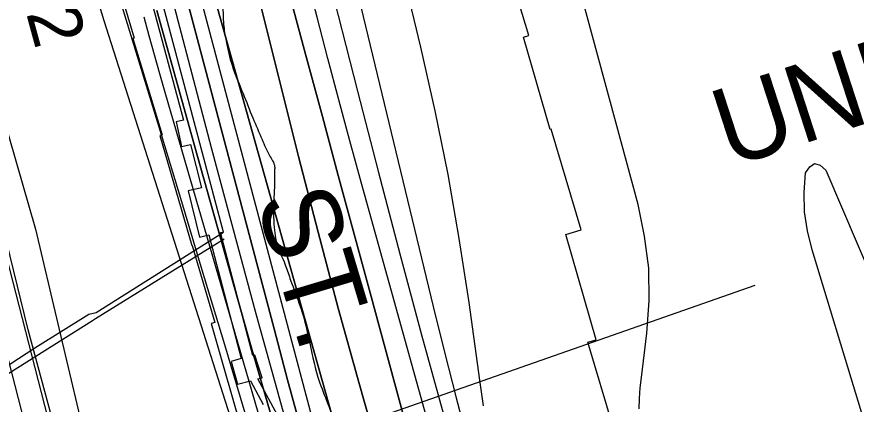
# Model space of a CAD drawing. Extents: x 3405885 to 3443815, y 558517 to 583997.
# Drawn here: x 3413539 to 3414615, y 577127 to 577623 of the extents above; entities that cross this region are included whole.
import ezdxf

# ---------------------------------------------------------------- set-up
doc = ezdxf.new("R2010")
doc.units = 0
for name, color, linetype in [('V-CHAN-DOCK', 7, 'Continuous'), ('V-FLOD-BASE', 7, 'Continuous'), ('V-LEVE-TOET', 7, 'Continuous'), ('V-RIVR-EDGE', 7, 'Continuous'), ('V-RIVR-RANG', 7, 'Continuous'), ('V-RRAP-RVMT', 7, 'Continuous'), ('V-RRAP-RVMT-IDEN', 7, 'Continuous'), ('V-SURV-LINE', 7, 'Continuous'), ('V-TOPO-DPTH', 7, 'Continuous'), ('V-TOPO-GNAM-IDEN', 7, 'Continuous'), ('V-TOPO-MAJR', 7, 'Continuous'), ('V-TOPO-MINR', 7, 'Continuous'), ('V-TOPO-WATR', 7, 'Continuous'), ('V-UTIL-LINE', 7, 'Continuous')]:
    doc.layers.add(name, color=color, linetype=linetype)

msp = doc.modelspace()

# ---------------------------------------------------------------- linework, layer by layer
at = {"layer": 'V-CHAN-DOCK'}
for points in [[(3414098.9, 576327.5), (3413981.9, 576772.3), (3413984.8, 576773), (3413976.8, 576806), (3413974, 576805.3), (3413906.9, 577051.1), (3413848.5, 577159.2), (3413854, 577160.6), (3413844.4, 577189.7), (3413841.9, 577189), (3413800.6, 577346.9), (3413804.2, 577347.4), (3413685.9, 577792.6)], [(3413710.8, 577648.5), (3413752.9, 577490.9), (3413743.5, 577488.6), (3413750.4, 577457.2), (3413762.1, 577459.5), (3413775.9, 577404.1), (3413759, 577400.3), (3413773.5, 577340.9), (3413785.5, 577343.7), (3413827.1, 577185.1), (3413814.2, 577181.6), (3413822.2, 577152.6), (3413838.8, 577156.7), (3413855.3, 577126.4)]]:
    msp.add_lwpolyline(points, dxfattribs=at)
at = {"layer": 'V-FLOD-BASE'}
msp.add_lwpolyline([(3413966.8, 575593.2), (3413930, 575533.2), (3413867.4, 575424.5), (3413866.3, 575435.7), (3413891.6, 575528.1), (3413926.7, 575661.7), (3413958.1, 575773.5), (3413962.9, 575792.9), (3413964.2, 575799.4), (3413964.2, 575804.7), (3413956.2, 575840.2), (3413920.9, 575949.5), (3413875.3, 576086.5), (3413833.1, 576215.9), (3413788.5, 576347.1), (3413730.7, 576515.5), (3413715.1, 576565.7), (3413696.7, 576641.3), (3413660.7, 576803.1), (3413634.6, 576914.3), (3413596.7, 577063.8), (3413554.1, 577222), (3413512.2, 577391.5)], dxfattribs=at)
at = {"layer": 'V-LEVE-TOET'}
msp.add_lwpolyline([(3413499, 577627.3), (3413496.6, 577619.1), (3413497.1, 577610.8), (3413502.2, 577577.8), (3413521.1, 577498.1), (3413563.2, 577351), (3413591.9, 577229.9), (3413633.2, 577054.6), (3413679.1, 576870.9), (3413715.7, 576698.5), (3413753.1, 576555.6), (3413784.9, 576453.4), (3413834.6, 576306.2), (3413880.9, 576173.3), (3413933, 576029.7), (3413974, 575893.8), (3413991.8, 575823.5), (3413994.1, 575811.1), (3413994, 575804.1), (3413975.8, 575718.7), (3413949.8, 575619.2)], dxfattribs=at)
at = {"layer": 'V-RIVR-EDGE'}
msp.add_spline([(3412820.9, 582098.3), (3412817.8, 582058), (3412815.6, 582029.5), (3412817.7, 582007.9), (3412825.7, 581980.1), (3412850.3, 581879.9), (3412863.7, 581832.7), (3412872, 581799.1), (3412892.3, 581722.3), (3412903.2, 581678.4), (3412909.6, 581634.8), (3412920.5, 581599), (3412934, 581569.3), (3412943.4, 581548.5), (3412954.7, 581511.2), (3412955.3, 581484.9), (3412959.7, 581464), (3412965.1, 581459.6), (3412977.9, 581445), (3412992.4, 581409.1), (3413006.5, 581353.1), (3413015.2, 581302.3), (3413018.7, 581260.3), (3413013.9, 581236.1), (3413008.8, 581220.1), (3413005.1, 581206.5), (3413003.6, 581194.5), (3413004.7, 581180.2), (3413009.3, 581149.1), (3413020.6, 581117.3), (3413042, 581073), (3413073, 581031.3), (3413081, 581018.1), (3413088.7, 580999.8), (3413094.4, 580977.9), (3413100.2, 580939.1), (3413102.7, 580912), (3413106.3, 580894.1), (3413113.5, 580861.9), (3413124.8, 580824.3), (3413140, 580781.4), (3413146.5, 580756.9), (3413148.7, 580740.1), (3413153.8, 580721.8), (3413161, 580692.6), (3413184.2, 580615.7), (3413194, 580582.5), (3413204.2, 580568.2), (3413207.8, 580561.6), (3413214, 580535.3), (3413232.1, 580461.7), (3413244, 580397.7), (3413253, 580345.1), (3413251.9, 580330.8), (3413256.4, 580258.4), (3413262.5, 580217.5), (3413264.6, 580175.4), (3413271.5, 580146.5), (3413278.7, 580117.3), (3413280.2, 580104.8), (3413276.4, 580060.6), (3413276.3, 580025.9), (3413275.6, 580012.4), (3413275.5, 580006.1), (3413277.7, 580003.2), (3413288, 580000.6), (3413298.6, 579998.4), (3413303.7, 579992.2), (3413305.5, 579985.2), (3413310.1, 579953.8), (3413314.5, 579931.1), (3413321, 579914.6), (3413327.2, 579894.5), (3413327.1, 579868.9), (3413323.4, 579842.6), (3413317.9, 579835.3), (3413316, 579824.7), (3413315.6, 579806.5), (3413320, 579780.1), (3413328, 579765.1), (3413335.6, 579758.2), (3413338.2, 579753.4), (3413338.9, 579747.5), (3413338.9, 579742.8), (3413335.5, 579730.7), (3413330.8, 579723.1), (3413327.8, 579714.3), (3413325.2, 579701.2), (3413326.7, 579689.5), (3413332.1, 579675.9), (3413338.3, 579668.2), (3413342.7, 579666.4), (3413352.6, 579666.7), (3413357.3, 579663.4), (3413365.3, 579652.4), (3413371.9, 579635.2), (3413374.8, 579618.4), (3413377.6, 579592.5), (3413379.4, 579557.4), (3413373.8, 579521.6), (3413375.2, 579501.1), (3413382.1, 579476.9), (3413395.1, 579440), (3413408.6, 579400.8), (3413417.6, 579358.8), (3413445.2, 579297.7), (3413449.9, 579271.7), (3413449.8, 579233.3), (3413439.5, 579191.3), (3413438.7, 579182.2), (3413439.8, 579172.7), (3413446, 579161.7), (3413464.9, 579134.6), (3413487.5, 579101.6), (3413497, 579074.9), (3413502.7, 579046.4), (3413506.7, 579018.2), (3413510.6, 578990.8), (3413518.6, 578952.4), (3413529.8, 578903.8), (3413538.1, 578871.6), (3413547.9, 578834.6), (3413558.4, 578787.4), (3413566.7, 578743.2), (3413574.6, 578699.3), (3413585.1, 578637.1), (3413595.2, 578577.2), (3413599.5, 578547.5), (3413610.7, 578516.1), (3413620.2, 578504), (3413626, 578499.2), (3413635.5, 578497), (3413635.9, 578494.4), (3413634.1, 578490.1), (3413632.2, 578487.1), (3413632.2, 578479.5), (3413633.2, 578455), (3413642.2, 578391), (3413644.3, 578359.2), (3413649, 578338.7), (3413656.3, 578322.2), (3413667.6, 578313.8), (3413676, 578309), (3413684.4, 578305.3), (3413688.8, 578300.2), (3413697.9, 578288.5), (3413702.2, 578272.4), (3413709.1, 578250.8), (3413714.9, 578233.2), (3413728.7, 578187.2), (3413734.8, 578151.3), (3413738.8, 578114.4), (3413740.5, 578084), (3413746.7, 578059.2), (3413750.7, 578043.4), (3413751.3, 578020), (3413747.6, 577990.8), (3413742, 577955), (3413736.9, 577934.5), (3413735.4, 577919.6), (3413733.5, 577904.2), (3413737.1, 577880.1), (3413741.4, 577864.7), (3413741.4, 577863.2), (3413750.2, 577865.8), (3413755, 577862.8), (3413760, 577845.7), (3413773.8, 577798.1), (3413781.8, 577765.2), (3413793, 577724.9), (3413797, 577700.4), (3413803.4, 577637.2), (3413804.4, 577613.8), (3413807.7, 577591.8), (3413815.3, 577561.1), (3413829.4, 577524.9), (3413841.8, 577493.8), (3413853.8, 577466), (3413863.2, 577445.5), (3413869.8, 577431.2), (3413869.8, 577426.1), (3413869.7, 577412.9), (3413868.9, 577389.5), (3413869.2, 577353), (3413871, 577339.8), (3413873.9, 577328.5), (3413883, 577306.5), (3413889.5, 577287.9), (3413905.1, 577244.3), (3413913.5, 577211), (3413925.4, 577161.3), (3413947.6, 577101.7), (3413958.8, 577073.5), (3413969, 577057.4), (3413973, 577043.8), (3413979.9, 577014.6), (3414002, 576930.8), (3414004.5, 576907.4), (3414006.3, 576897.2), (3414015, 576880.3), (3414024.5, 576858.8), (3414031.3, 576835.7), (3414040.8, 576799.5), (3414054.2, 576750.1), (3414062.5, 576713.9), (3414069.3, 576679.9), (3414074.4, 576668.5), (3414075.1, 576663.4), (3414103.1, 576586.2), (3414107.4, 576564.6), (3414115.4, 576529.2), (3414119, 576508), (3414142.2, 576433.7), (3414153.5, 576399.3), (3414159.6, 576378.5), (3414164.7, 576348.8), (3414174.1, 576303.8), (3414178, 576275), (3414184.1, 576248.3), (3414191.1, 576234), (3414204.1, 576202.1), (3414212.1, 576179.5), (3414243, 576089.5), (3414264.8, 576025.4), (3414269.5, 576005.7), (3414269.4, 575994.4), (3414267.6, 575989.1)], degree=3, dxfattribs=at)
at = {"layer": 'V-RIVR-RANG'}
msp.add_line((3413598.5, 576968.9), (3414485.8, 577279.2), dxfattribs=at)
at = {"layer": 'V-RRAP-RVMT'}
for points in [[(3414453.7, 576492.6), (3414409.1, 576621.8), (3414406.4, 576620.8), (3414365.7, 576741.2), (3414359.7, 576739.2), (3414321.2, 576853), (3414317.2, 576851.7), (3414285.6, 576951.7), (3414313.7, 576960.2), (3414275.4, 577087.5), (3414304, 577096), (3414271.4, 577206.1), (3414281.9, 577209.2), (3414243, 577344.3), (3414262.9, 577350.2), (3414224.5, 577479.4), (3414222.9, 577478.9), (3414188.7, 577597.3), (3414195.6, 577599.4), (3414154.2, 577736.4)], [(3413652.8, 577721.4), (3413690, 577595.9), (3413688.2, 577595.4), (3413725.6, 577471.8), (3413722.8, 577471), (3413763.6, 577330.1), (3413764, 577330.2), (3413793.3, 577231.6), (3413788.3, 577230.2), (3413831.8, 577079.3), (3413835.3, 577080.3), (3413865.5, 576978.7), (3413855.2, 576975.6), (3413892.6, 576851.5), (3413887.4, 576849.9), (3413928.5, 576720.2), (3413923, 576718.4), (3413961.4, 576604.5), (3413956, 576602.7), (3413997.6, 576479.5)]]:
    msp.add_lwpolyline(points, dxfattribs=at)
at = {"layer": 'V-SURV-LINE'}
for points in [[(3413574.1, 577007.7), (3412835.6, 579881.8)], [(3412864.6, 579889.2), (3413603.1, 577015.1)]]:
    msp.add_lwpolyline(points, dxfattribs=at)
at = {"layer": 'V-TOPO-DPTH'}
for points in [[(3413870.4, 577720.3), (3413910.7, 577570.7), (3413931, 577495.3), (3413951.4, 577420), (3413971.8, 577344.6), (3413992.3, 577269.3), (3414092.8, 576899.2), (3414095.8, 576888.3), (3414098.8, 576877.5), (3414101.9, 576866.6), (3414105, 576855.8), (3414108.2, 576844.9), (3414111.5, 576834.2), (3414114.9, 576823.4), (3414118.4, 576812.7), (3414340.3, 576140.2), (3414345.1, 576125.9), (3414350, 576111.6), (3414355.1, 576097.4), (3414360.2, 576083.2), (3414623.5, 575371.4)], [(3413870.4, 577720.3), (3413910.7, 577570.7), (3413931, 577495.3), (3413951.4, 577420), (3413971.8, 577344.6), (3413992.3, 577269.3), (3414092.8, 576899.2), (3414095.8, 576888.3), (3414098.8, 576877.5), (3414101.9, 576866.6), (3414105, 576855.8), (3414108.2, 576844.9), (3414111.5, 576834.2), (3414114.9, 576823.4), (3414118.4, 576812.7), (3414340.3, 576140.2), (3414345.1, 576125.9), (3414350, 576111.6), (3414355.1, 576097.4), (3414360.2, 576083.2), (3414623.5, 575371.4)], [(3414176.3, 576509.8), (3414149.5, 576591.8), (3414072.6, 576829.5), (3414067.2, 576846.7), (3414061.8, 576864), (3414056.5, 576881.3), (3414051.4, 576898.6), (3414005.4, 577056.7), (3413978, 577153.3), (3413951.2, 577250), (3413925.5, 577347), (3413900.6, 577444.3), (3413843.2, 577673.7)], [(3414176.3, 576509.8), (3414149.5, 576591.8), (3414072.6, 576829.5), (3414067.2, 576846.7), (3414061.8, 576864), (3414056.5, 576881.3), (3414051.4, 576898.6), (3414005.4, 577056.7), (3413978, 577153.3), (3413951.2, 577250), (3413925.5, 577347), (3413900.6, 577444.3), (3413843.2, 577673.7)], [(3413754, 577659.2), (3413869.2, 577223.1), (3413886.5, 577157.9), (3413904.1, 577092.8), (3413922, 577027.8), (3413940.2, 576962.9), (3413969.6, 576858.5), (3413973.2, 576845.8), (3413976.8, 576833.1), (3413980.4, 576820.4), (3413984.1, 576807.7), (3414083.7, 576466.7)], [(3414083.7, 576466.7), (3413984.1, 576807.7), (3413980.4, 576820.4), (3413976.8, 576833.1), (3413973.2, 576845.8), (3413969.6, 576858.5), (3413940.2, 576962.9), (3413922, 577027.8), (3413904.1, 577092.8), (3413886.5, 577157.9), (3413869.2, 577223.1), (3413754, 577659.2)], [(3413669.5, 577652.8), (3413721.3, 577482.2), (3413749, 577390.6), (3413776.6, 577299), (3413804.2, 577207.3), (3413831.6, 577115.6), (3413917.5, 576827.7), (3413919.7, 576820.4), (3413921.8, 576813.1), (3413923.9, 576805.8), (3413925.9, 576798.4), (3413944.3, 576731.5), (3413955.5, 576690.7), (3413966.4, 576649.8), (3413977.1, 576608.8), (3413987.7, 576567.8), (3414103.6, 576111.6)], [(3413718.9, 577631.5), (3413770.4, 577445.8), (3413839.6, 577200.4), (3413913, 576949), (3413952.7, 576812.7), (3414019.4, 576571.6), (3414062.4, 576415.7), (3414113.9, 576220.6), (3414156.9, 576063), (3414193.2, 575932.6), (3414227.8, 575803.1), (3414306.3, 575543.2), (3414400.9, 575243.3), (3414476.2, 575016.6), (3414482.1, 574999.6), (3414486.3, 574987.7), (3414536.2, 574860.7), (3414616.6, 574655.3)], [(3414616.6, 574655.3), (3414536.2, 574860.7), (3414486.3, 574987.7), (3414482.1, 574999.6), (3414476.2, 575016.6), (3414400.9, 575243.3), (3414306.3, 575543.2), (3414227.8, 575803.1), (3414193.2, 575932.6), (3414156.9, 576063), (3414113.9, 576220.6), (3414062.4, 576415.7), (3414019.4, 576571.6), (3413952.7, 576812.7), (3413913, 576949), (3413839.6, 577200.4), (3413770.4, 577445.8), (3413718.9, 577631.5)], [(3414626.9, 575077.5), (3414533.7, 575346.5), (3414490.7, 575470.4), (3414447.6, 575594.3), (3414404.3, 575718.2), (3414360.9, 575841.9), (3414304.1, 576003.7), (3414289, 576046.6), (3414273.9, 576089.5), (3414258.9, 576132.3), (3414243.8, 576175.2), (3414185.4, 576341.3), (3414156.2, 576425.3), (3414127.5, 576509.5), (3414099.5, 576594), (3414072, 576678.6), (3414043, 576769.2), (3414030.6, 576808.6), (3414018.4, 576848.2), (3414006.7, 576887.9), (3413995.3, 576927.6), (3413796.5, 577634.1)], [(3413796.5, 577634.1), (3413995.3, 576927.6), (3414006.7, 576887.9), (3414018.4, 576848.2), (3414030.6, 576808.6), (3414043, 576769.2), (3414072, 576678.6), (3414099.5, 576594), (3414127.5, 576509.5), (3414156.2, 576425.3), (3414185.4, 576341.3), (3414243.8, 576175.2), (3414258.9, 576132.3), (3414273.9, 576089.5), (3414289, 576046.6), (3414304.1, 576003.7), (3414360.9, 575841.9), (3414404.3, 575718.2), (3414447.6, 575594.3), (3414490.7, 575470.4), (3414533.7, 575346.5), (3414626.9, 575077.5)]]:
    msp.add_lwpolyline(points, dxfattribs=at)
at = {"layer": 'V-TOPO-MAJR'}
msp.add_lwpolyline([(3414242.8, 576506.9), (3414146, 576823.2), (3414136.3, 576855.4), (3414126.7, 576887.6), (3414117.5, 576919.9), (3414108.3, 576952.2), (3413980.9, 577411.4), (3413966.4, 577464.2), (3413952.1, 577517), (3413938.1, 577569.9), (3413924.2, 577622.8), (3413903.4, 577703.2)], dxfattribs=at)
at = {"layer": 'V-TOPO-MINR'}
for points in [[(3414337, 577120.7), (3414337.5, 577134.1), (3414338.5, 577147.5), (3414339.9, 577160.8), (3414347.1, 577217.8), (3414349.9, 577259.4), (3414349.4, 577300.9), (3414344.1, 577342), (3414335.6, 577382.8), (3414233.8, 577759.3)], [(3414623.5, 575371.4), (3414360.2, 576083.2), (3414355.1, 576097.4), (3414350, 576111.6), (3414345.1, 576125.9), (3414340.3, 576140.2), (3414118.4, 576812.7), (3414114.9, 576823.4), (3414111.5, 576834.2), (3414108.2, 576844.9), (3414105, 576855.8), (3414101.9, 576866.6), (3414098.8, 576877.5), (3414095.8, 576888.3), (3414092.8, 576899.2), (3413992.3, 577269.3), (3413971.8, 577344.6), (3413951.4, 577420), (3413931, 577495.3), (3413910.7, 577570.7), (3413870.4, 577720.3)], [(3414025.5, 577714.1), (3414056.8, 577584.2), (3414075.1, 577502.9), (3414091.8, 577421.3), (3414106.1, 577339.2), (3414118.7, 577256.9), (3414132.4, 577157.7), (3414137.3, 577124.8)], [(3413766.1, 577680.1), (3413946.4, 577000.4), (3413953.7, 576973.3), (3413961, 576946.3), (3413968.4, 576919.3), (3413975.9, 576892.2), (3413988, 576849), (3413989.5, 576843.7), (3413991.1, 576838.3), (3413992.6, 576832.9), (3413994.2, 576827.5), (3414018.5, 576746.5), (3414032.6, 576700.7), (3414046.9, 576655), (3414061.7, 576609.5), (3414076.8, 576564.1), (3414222.6, 576132.9)], [(3413936.5, 577683.9), (3413976.2, 577527.7), (3414003, 577423.6), (3414030.3, 577319.6), (3414058.2, 577215.8), (3414086.7, 577112.1), (3414134.8, 576938.6), (3414141, 576916.8), (3414147.3, 576895.1), (3414153.9, 576873.4), (3414160.6, 576851.8), (3414309.9, 576379.8), (3414323.7, 576337.1), (3414338, 576294.6), (3414352.7, 576252.2), (3414367.9, 576210), (3414371.6, 576200), (3414385.5, 576163), (3414399.7, 576126.1), (3414414.4, 576089.5), (3414429.4, 576052.9), (3414787.8, 575198.5)], [(3413843.2, 577673.7), (3413900.6, 577444.3), (3413925.5, 577347), (3413951.2, 577250), (3413978, 577153.3), (3414005.4, 577056.7), (3414051.4, 576898.6), (3414056.5, 576881.3), (3414061.8, 576864), (3414067.2, 576846.7), (3414072.6, 576829.5), (3414149.5, 576591.8), (3414176.3, 576509.8)], [(3413754, 577659.2), (3413869.2, 577223.1), (3413886.5, 577157.9), (3413904.1, 577092.8), (3413922, 577027.8), (3413940.2, 576962.9), (3413969.6, 576858.5), (3413973.2, 576845.8), (3413976.8, 576833.1), (3413980.4, 576820.4), (3413984.1, 576807.7), (3414083.7, 576466.7)], [(3413974.3, 577661.1), (3414073.2, 577251.9), (3414087.7, 577193.3), (3414102.5, 577134.8), (3414117.8, 577076.4), (3414133.5, 577018.1), (3414158.7, 576926.4), (3414162.2, 576914.1), (3414165.7, 576901.8), (3414169.5, 576889.6), (3414173.3, 576877.4), (3414216, 576745.1), (3414241.8, 576667), (3414268.4, 576589.1), (3414296, 576511.6), (3414324.3, 576434.3), (3414421.5, 576174.6), (3414428.7, 576155.6), (3414436.1, 576136.7), (3414443.6, 576117.8), (3414451.2, 576099), (3414563.2, 575827), (3414608.9, 575716.2), (3414654.8, 575605.5)], [(3413669.5, 577652.8), (3413721.3, 577482.2), (3413749, 577390.6), (3413776.6, 577299), (3413804.2, 577207.3), (3413831.6, 577115.6), (3413917.5, 576827.7), (3413919.7, 576820.4), (3413921.8, 576813.1), (3413923.9, 576805.8), (3413925.9, 576798.4), (3413944.3, 576731.5), (3413955.5, 576690.7), (3413966.4, 576649.8), (3413977.1, 576608.8), (3413987.7, 576567.8), (3414103.6, 576111.6)], [(3413644.9, 577638.2), (3413651, 577618.4), (3413893.6, 576857), (3413896.2, 576848.9), (3413898.7, 576840.8), (3413901.2, 576832.7), (3413903.7, 576824.6), (3413908.3, 576809.5), (3413908.9, 576807.7), (3413909, 576807.2), (3413910.4, 576801.9), (3413911.3, 576798.7), (3413912.2, 576795.5), (3413913, 576792.3), (3413913.8, 576789.1), (3414091.8, 576071)], [(3413740.9, 577636.5), (3413788.5, 577455.6), (3413816.5, 577350.7), (3413844.8, 577245.9), (3413873.8, 577141.3), (3413903.2, 577036.8), (3413946.6, 576884.2), (3413954.6, 576856.1), (3413962.5, 576827.9), (3413970.5, 576799.8), (3413978.5, 576771.6), (3414144, 576188.2)], [(3413796.5, 577634.1), (3413995.3, 576927.6), (3414006.7, 576887.9), (3414018.4, 576848.2), (3414030.6, 576808.6), (3414043, 576769.2), (3414072, 576678.6), (3414099.5, 576594), (3414127.5, 576509.5), (3414156.2, 576425.3), (3414185.4, 576341.3), (3414243.8, 576175.2), (3414258.9, 576132.3), (3414273.9, 576089.5), (3414289, 576046.6), (3414304.1, 576003.7), (3414360.9, 575841.9), (3414404.3, 575718.2), (3414447.6, 575594.3), (3414490.7, 575470.4), (3414533.7, 575346.5), (3414626.9, 575077.5)], [(3413702.2, 577623.3), (3413708.8, 577599.1), (3413715.5, 577574.8), (3413722.3, 577550.7), (3413729.2, 577526.5), (3413926.9, 576846.2), (3413931, 576832.1), (3413935.1, 576817.9), (3413939.1, 576803.8), (3413943, 576789.7), (3413980.1, 576656.3), (3414002.4, 576575.5), (3414024.4, 576494.6)], [(3414628, 577097), (3414558.7, 577324.6), (3414552.9, 577348.9), (3414549.2, 577373.4), (3414548.7, 577398.2), (3414550.3, 577423.2), (3414555.8, 577431.1), (3414562, 577435), (3414568.9, 577432.9), (3414576.5, 577426.8), (3414699.4, 577138.9)]]:
    msp.add_lwpolyline(points, dxfattribs=at)
at = {"layer": 'V-TOPO-WATR'}
msp.add_lwpolyline([(3414616.6, 574655.3), (3414536.2, 574860.7), (3414486.3, 574987.7), (3414482.1, 574999.6), (3414476.2, 575016.6), (3414400.9, 575243.3), (3414306.3, 575543.2), (3414227.8, 575803.1), (3414193.2, 575932.6), (3414156.9, 576063), (3414113.9, 576220.6), (3414062.4, 576415.7), (3414019.4, 576571.6), (3413952.7, 576812.7), (3413913, 576949), (3413839.6, 577200.4), (3413770.4, 577445.8), (3413718.9, 577631.5)], dxfattribs=at)
at = {"layer": 'V-UTIL-LINE'}
for points in [[(3413300.4, 577012), (3413317.6, 577024.3), (3413376.1, 577069.5), (3413380.8, 577080.7), (3413562.6, 577199.1), (3413631.6, 577242.3), (3413640.9, 577244.2), (3413804.5, 577347.4)], [(3413805.3, 577338.3), (3413640.2, 577236.3), (3413636.2, 577233.7), (3413490.9, 577142.1), (3413381.4, 577072.8), (3413377.4, 577062.2), (3413263.8, 576975.8), (3413095.8, 576844.7), (3412972.2, 576749.7), (3412978.1, 576743.7), (3413050.8, 576645.5), (3413142, 576634.3)]]:
    msp.add_lwpolyline(points, dxfattribs=at)

# ---------------------------------------------------------------- texts
at = {"layer": 'V-RIVR-RANG'}
msp.add_text('20.2', height=67, rotation=285.1983, dxfattribs=at).set_placement((3413518.5, 577748.2))
at = {"layer": 'V-RRAP-RVMT-IDEN'}
msp.add_text('ST.', height=100, rotation=286.6994, dxfattribs=at).set_placement((3413845.3, 577388.6))
at = {"layer": 'V-TOPO-GNAM-IDEN'}
msp.add_text('UNION LDG.', height=100, rotation=17.9709, dxfattribs=at).set_placement((3414452.3, 577429.4))

doc.saveas('drawing.dxf')
